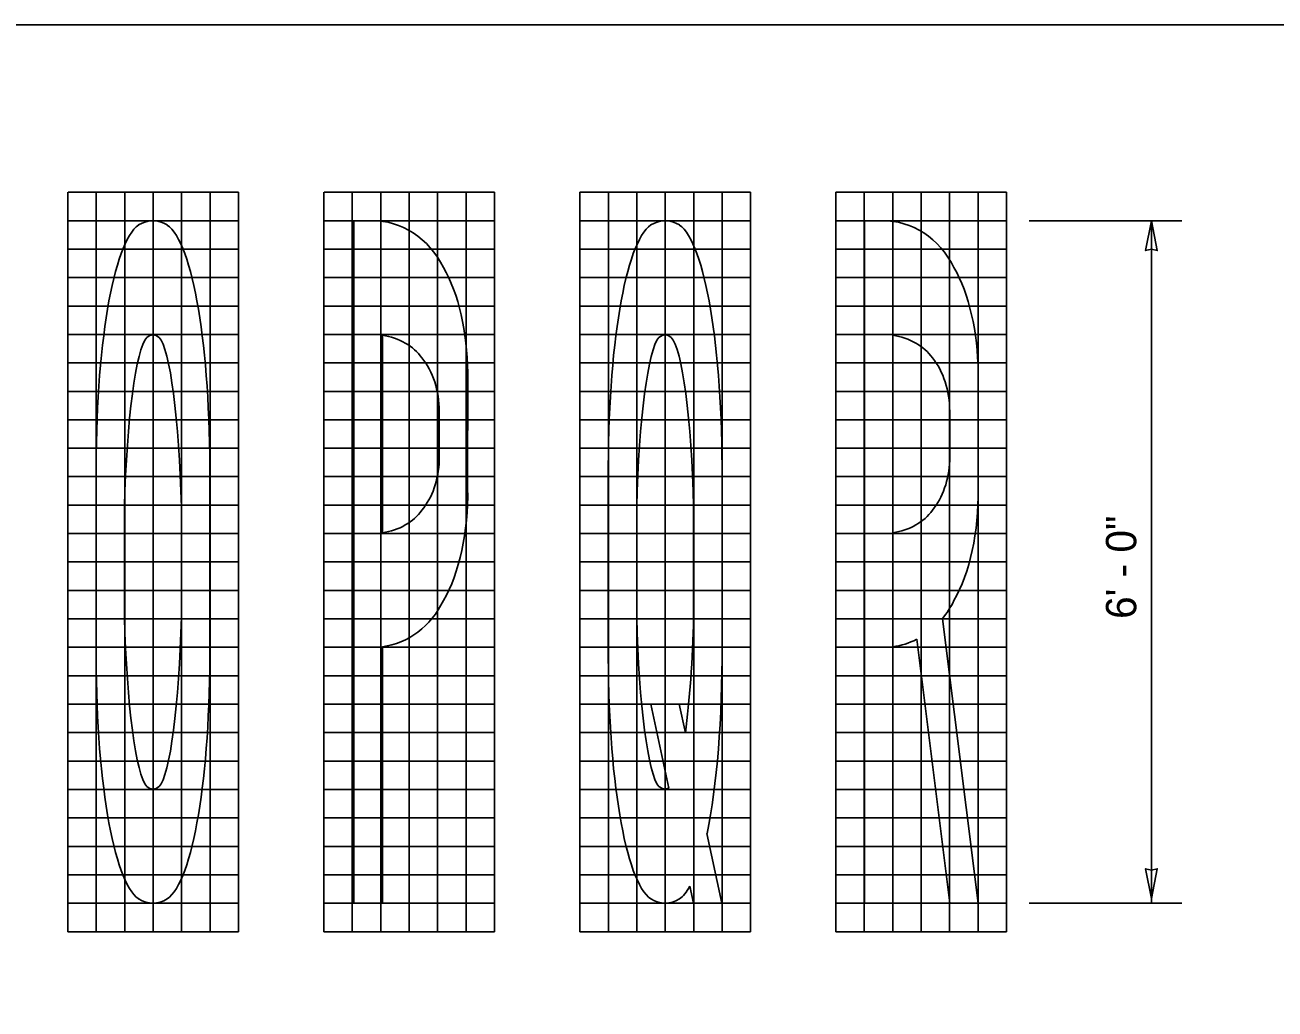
# Model space of a CAD drawing. Extents: x 99862 to 103151, y 100000 to 102076.
# Drawn here: x 101833 to 102492, y 101556 to 102076 of the extents above; entities that cross this region are included whole.
import ezdxf

# ---------------------------------------------------------------- set-up
doc = ezdxf.new("R2010")
doc.units = 0
for name, color, linetype in [('Level 1', 7, 'Continuous'), ('Level 15', 7, 'Continuous'), ('Level 20', 7, 'Continuous'), ('Level 4', 7, 'Continuous')]:
    doc.layers.add(name, color=color, linetype=linetype)

msp = doc.modelspace()

# ---------------------------------------------------------------- linework, layer by layer
at = {"layer": 'Level 1'}
msp.add_lwpolyline([(99862, 99999.5), (103151, 99999.5), (103151, 102075.5), (99862, 102075.5)], close=True, dxfattribs=at)
at = {"layer": 'Level 15'}
for p, q in [((102362.43, 101972.28), (102442.83, 101972.28)), ((102426.83, 101612.28), (102426.83, 101972.28)), ((102362.43, 101612.28), (102442.83, 101612.28))]:
    msp.add_line(p, q, dxfattribs=at)
for points in [[(102426.83, 101972.28), (102423.75, 101956.55), (102426.83, 101957.28), (102429.92, 101956.55)], [(102426.83, 101614.78), (102423.75, 101630.5), (102426.83, 101629.78), (102429.92, 101630.5)]]:
    msp.add_lwpolyline(points, close=True, dxfattribs=at)
at = {"layer": 'Level 20'}
for p, q in [((102013.83, 101972.28), (102006.33, 101972.28)), ((102006.33, 101972.28), (102006.33, 101612.28)), ((102015.72, 101972.27), (102013.83, 101972.28)), ((102282.96, 101972.28), (102275.46, 101972.28)), ((102275.46, 101972.28), (102275.46, 101612.28)), ((102284.86, 101972.27), (102282.96, 101972.28)), ((102021.33, 101807.68), (102021.33, 101911.84)), ((102290.46, 101807.68), (102290.46, 101911.84)), ((102066.31, 101830.95), (102066.33, 101892.06)), ((102335.45, 101830.95), (102335.46, 101892.06)), ((102051.33, 101869.39), (102051.33, 101845.83)), ((102320.46, 101869.39), (102320.46, 101845.83)), ((101870.41, 101836.34), (101870.41, 101792.28)), ((101930.39, 101792.28), (101930.39, 101836.34)), ((102140.44, 101836.34), (102140.44, 101792.28)), ((102200.42, 101748.22), (102200.42, 101836.34)), ((101885.4, 101792.28), (101885.4, 101821.34)), ((101915.4, 101821.34), (101915.4, 101792.28)), ((102155.44, 101763.22), (102155.44, 101821.34)), ((102185.43, 101821.34), (102185.43, 101792.28)), ((101870.41, 101792.28), (101870.41, 101748.22)), ((101885.4, 101763.22), (101885.4, 101792.28)), ((101915.4, 101792.28), (101915.4, 101763.22)), ((101930.39, 101748.22), (101930.39, 101792.28)), ((102140.44, 101792.28), (102140.44, 101748.22)), ((102185.43, 101792.28), (102185.43, 101763.22)), ((102316.71, 101762.28), (102316.46, 101762.28)), ((102335.46, 101612.28), (102316.71, 101762.28)), ((102303.07, 101751.48), (102320.46, 101612.28)), ((102021.33, 101612.28), (102021.33, 101747.57)), ((102290.46, 101612.28), (102290.46, 101747.57)), ((102177.87, 101717.28), (102162.88, 101717.28)), ((102162.88, 101717.28), (102172.37, 101672.98)), ((102181.1, 101702.22), (102177.87, 101717.28)), ((102200.37, 101612.28), (102192.5, 101649.01)), ((102183.45, 101621.24), (102185.37, 101612.28)), ((102006.33, 101612.28), (102021.33, 101612.28)), ((102185.37, 101612.28), (102200.37, 101612.28)), ((102275.46, 101612.28), (102290.46, 101612.28)), ((102320.46, 101612.28), (102335.46, 101612.28))]:
    msp.add_line(p, q, dxfattribs=at)
for centre, major_axis, ratio, start_param, end_param in [((101892.9, 101656.7), (-7.85, -315.58), 0.19927, 3.02647, 3.266464), ((102016.42, 101924.16), (0, -48.11), 0.883106, 2.078693, 3.158066), ((102162.93, 101656.7), (-7.85, -315.58), 0.19927, 3.02647, 3.266464), ((102285.56, 101924.16), (0, -48.11), 0.883106, 2.078693, 3.158066), ((101900.4, 101821.97), (3.75, -149.37), 0.19927, 3.270148, 4.611013), ((101900.41, 101822.04), (-3.72, -149.3), 0.19927, 1.671693, 3.012646), ((102170.43, 101821.97), (3.75, -149.37), 0.19927, 3.270148, 4.611013), ((102170.45, 101822.04), (-3.72, -149.3), 0.19927, 1.671693, 3.012646), ((102030.69, 101891.02), (0, -73.69), 0.483719, 1.584917, 2.445445), ((102299.82, 101891.02), (0, -73.69), 0.483719, 1.584917, 2.445445), ((101896.42, 101821.09), (-2.11, -90.25), 0.122012, 3.268533, 4.71248), ((101894.43, 101651.68), (-6.09, -260.36), 0.122012, 3.042541, 3.248082), ((101904.39, 101821.09), (2.11, -90.25), 0.122012, 1.570705, 3.018849), ((102015.84, 101888.35), (30.13, 0), 0.792657, 0.505828, 1.38755), ((102166.45, 101821.09), (-2.11, -90.25), 0.122012, 3.268533, 4.71248), ((102164.47, 101651.68), (-6.09, -260.36), 0.122012, 3.042541, 3.248082), ((102174.42, 101821.09), (2.11, -90.25), 0.122012, 1.570705, 3.018849), ((102284.97, 101888.35), (30.13, 0), 0.792657, 0.505828, 1.38755), ((102025.89, 101871.67), (0, -36.82), 0.691027, 1.570796, 2.445559), ((102295.02, 101871.67), (0, -36.82), 0.691027, 1.570796, 2.445559), ((102025.89, 101871.67), (0, -36.82), 0.691027, 1.529951, 1.570796), ((102025.88, 101870.07), (2.31, -36.7), 0.691023, 1.508615, 1.52981), ((102295.02, 101871.67), (0, -36.82), 0.691027, 1.529951, 1.570796), ((102295.01, 101870.07), (2.31, -36.7), 0.691023, 1.508615, 1.52981), ((102026.04, 101847.81), (-0.1, -36.69), 0.690438, 0.696034, 1.518966), ((102295.17, 101847.81), (-0.1, -36.69), 0.690438, 0.696034, 1.518966), ((102030.71, 101828.49), (0, -73.71), 0.483307, 0.696034, 1.604189), ((102299.84, 101828.49), (0, -73.71), 0.483307, 0.696034, 1.604189), ((102015.84, 101831.18), (30.13, 0), 0.793333, 4.895635, 5.777357), ((102284.97, 101831.18), (30.13, 0), 0.793333, 4.895635, 5.777357), ((102016.64, 101795.09), (0, -47.81), 0.882353, 0.111341, 1.064968), ((102285.78, 101795.09), (0, -47.81), 0.882353, 0.814442, 1.064968), ((101896.42, 101763.47), (2.11, -90.25), 0.122012, 4.712298, 6.156245), ((101904.39, 101763.47), (-2.11, -90.25), 0.122012, 0.122744, 1.570888), ((102166.45, 101763.47), (2.11, -90.25), 0.122012, 4.712298, 6.156245), ((102174.42, 101763.47), (-2.11, -90.25), 0.122012, 0.827749, 1.570888), ((102285.78, 101795.09), (0, -47.81), 0.882353, 0.111341, 0.422215), ((101900.4, 101762.59), (-3.75, -149.37), 0.19927, 4.813765, 6.15463), ((101900.41, 101762.52), (3.72, -149.3), 0.19927, 0.128946, 1.4699), ((102170.43, 101762.59), (-3.75, -149.37), 0.19927, 4.813765, 6.15463), ((102170.45, 101762.52), (3.72, -149.3), 0.19927, 0.702167, 1.4699), ((101894.43, 101932.88), (6.09, -260.36), 0.122012, 6.176696, 6.382237), ((102164.47, 101932.88), (6.09, -260.36), 0.122012, 6.176696, 6.340383), ((102170.45, 101762.52), (3.72, -149.3), 0.19927, 0.128946, 0.324404), ((101892.9, 101927.86), (7.85, -315.58), 0.19927, 6.158314, 6.398307), ((102162.93, 101927.86), (7.85, -315.58), 0.19927, 6.158314, 6.398307)]:
    msp.add_ellipse(centre, major_axis=major_axis, ratio=ratio, start_param=start_param, end_param=end_param, dxfattribs=at)
at = {"layer": 'Level 4'}
for p, q in [((101855.5, 101987.28), (101855.5, 101597.28)), ((101855.61, 101987.28), (101945.5, 101987.28)), ((101870.5, 101987.28), (101870.5, 101597.28)), ((101885.5, 101987.28), (101885.5, 101597.28)), ((101900.5, 101987.28), (101900.5, 101597.28)), ((101915.5, 101987.28), (101915.5, 101597.28)), ((101930.5, 101987.28), (101930.5, 101597.28)), ((101945.5, 101987.28), (101945.5, 101597.28)), ((101990.5, 101987.28), (101990.5, 101597.28)), ((101990.59, 101987.28), (102080.5, 101987.28)), ((102005.5, 101987.28), (102005.5, 101597.28)), ((102020.5, 101987.28), (102020.5, 101597.28)), ((102035.5, 101987.28), (102035.5, 101597.28)), ((102050.5, 101987.28), (102050.5, 101597.28)), ((102065.5, 101987.28), (102065.5, 101597.28)), ((102080.5, 101987.28), (102080.5, 101597.28)), ((102125.5, 101987.28), (102125.5, 101597.28)), ((102125.52, 101987.28), (102215.5, 101987.28)), ((102140.5, 101987.28), (102140.5, 101597.28)), ((102155.5, 101987.28), (102155.5, 101597.28)), ((102170.5, 101987.28), (102170.5, 101597.28)), ((102185.5, 101987.28), (102185.5, 101597.28)), ((102200.5, 101987.28), (102200.5, 101597.28)), ((102215.5, 101987.28), (102215.5, 101597.28)), ((102260.36, 101987.28), (102350.43, 101987.28)), ((102260.43, 101987.28), (102260.43, 101597.28)), ((102275.43, 101987.28), (102275.43, 101597.28)), ((102290.43, 101987.28), (102290.43, 101597.28)), ((102305.43, 101987.28), (102305.43, 101597.28)), ((102320.43, 101987.28), (102320.43, 101597.28)), ((102335.43, 101987.28), (102335.43, 101597.28)), ((102350.43, 101987.28), (102350.43, 101597.28)), ((101855.43, 101972.28), (101945.5, 101972.28)), ((101990.43, 101972.28), (102080.5, 101972.28)), ((102125.43, 101972.28), (102215.5, 101972.28)), ((102260.36, 101972.28), (102350.43, 101972.28)), ((101855.43, 101957.28), (101945.5, 101957.28)), ((101990.43, 101957.28), (102080.5, 101957.28)), ((102125.43, 101957.28), (102215.5, 101957.28)), ((102260.36, 101957.28), (102350.43, 101957.28)), ((101855.64, 101942.28), (101945.5, 101942.28)), ((101990.64, 101942.28), (102080.5, 101942.28)), ((102125.64, 101942.28), (102215.5, 101942.28)), ((102260.57, 101942.28), (102350.43, 101942.28)), ((101855.43, 101927.28), (101945.5, 101927.28)), ((101990.43, 101927.28), (102080.5, 101927.28)), ((102125.43, 101927.28), (102215.5, 101927.28)), ((102260.36, 101927.28), (102350.43, 101927.28)), ((101855.43, 101912.28), (101945.5, 101912.28)), ((101990.43, 101912.28), (102080.5, 101912.28)), ((102125.43, 101912.28), (102215.5, 101912.28)), ((102260.36, 101912.28), (102350.43, 101912.28)), ((101855.54, 101897.28), (101945.5, 101897.28)), ((101990.54, 101897.28), (102080.5, 101897.28)), ((102125.54, 101897.28), (102215.5, 101897.28)), ((102260.47, 101897.28), (102350.43, 101897.28)), ((101855.54, 101882.28), (101945.5, 101882.28)), ((101990.54, 101882.28), (102080.5, 101882.28)), ((102125.54, 101882.28), (102215.5, 101882.28)), ((102260.47, 101882.28), (102350.43, 101882.28)), ((101855.64, 101867.28), (101945.5, 101867.28)), ((101990.64, 101867.28), (102080.5, 101867.28)), ((102125.64, 101867.28), (102215.5, 101867.28)), ((102260.57, 101867.28), (102350.43, 101867.28)), ((101855.64, 101852.28), (101945.5, 101852.28)), ((101990.64, 101852.28), (102080.5, 101852.28)), ((102125.64, 101852.28), (102215.5, 101852.28)), ((102260.57, 101852.28), (102350.43, 101852.28)), ((101855.43, 101837.28), (101945.5, 101837.28)), ((101990.43, 101837.28), (102080.5, 101837.28)), ((102125.43, 101837.28), (102215.5, 101837.28)), ((102260.36, 101837.28), (102350.43, 101837.28)), ((101855.54, 101822.28), (101945.5, 101822.28)), ((101990.54, 101822.28), (102080.5, 101822.28)), ((102125.54, 101822.28), (102215.5, 101822.28)), ((102260.47, 101822.28), (102350.43, 101822.28)), ((101855.43, 101807.28), (101945.5, 101807.28)), ((101990.43, 101807.28), (102080.5, 101807.28)), ((102125.43, 101807.28), (102215.5, 101807.28)), ((102260.36, 101807.28), (102350.43, 101807.28)), ((101855.54, 101792.28), (101945.5, 101792.28)), ((101990.54, 101792.28), (102080.5, 101792.28)), ((102125.54, 101792.28), (102215.5, 101792.28)), ((102260.47, 101792.28), (102350.43, 101792.28)), ((101855.54, 101777.28), (101945.5, 101777.28)), ((101990.54, 101777.28), (102080.5, 101777.28)), ((102125.54, 101777.28), (102215.5, 101777.28)), ((102260.47, 101777.28), (102350.43, 101777.28)), ((101855.43, 101762.28), (101945.5, 101762.28)), ((101990.43, 101762.28), (102080.5, 101762.28)), ((102125.43, 101762.28), (102215.5, 101762.28)), ((102260.36, 101762.28), (102350.43, 101762.28)), ((101855.54, 101747.28), (101945.5, 101747.28)), ((101990.54, 101747.28), (102080.5, 101747.28)), ((102125.54, 101747.28), (102215.5, 101747.28)), ((102260.47, 101747.28), (102350.43, 101747.28)), ((101855.54, 101732.28), (101945.5, 101732.28)), ((101990.54, 101732.28), (102080.5, 101732.28)), ((102125.54, 101732.28), (102215.5, 101732.28)), ((102260.47, 101732.28), (102350.43, 101732.28)), ((101855.54, 101717.28), (101945.5, 101717.28)), ((101990.54, 101717.28), (102080.5, 101717.28)), ((102125.54, 101717.28), (102215.5, 101717.28)), ((102260.47, 101717.28), (102350.43, 101717.28)), ((101855.54, 101702.28), (101945.5, 101702.28)), ((101990.54, 101702.28), (102080.5, 101702.28)), ((102125.54, 101702.28), (102215.5, 101702.28)), ((102260.47, 101702.28), (102350.43, 101702.28)), ((101855.54, 101687.28), (101945.5, 101687.28)), ((101990.54, 101687.28), (102080.5, 101687.28)), ((102125.54, 101687.28), (102215.5, 101687.28)), ((102260.47, 101687.28), (102350.43, 101687.28)), ((101855.64, 101672.28), (101945.5, 101672.28)), ((101990.64, 101672.28), (102080.5, 101672.28)), ((102125.64, 101672.28), (102215.5, 101672.28)), ((102260.57, 101672.28), (102350.43, 101672.28)), ((101855.54, 101657.28), (101945.5, 101657.28)), ((101990.54, 101657.28), (102080.5, 101657.28)), ((102125.54, 101657.28), (102215.5, 101657.28)), ((102260.47, 101657.28), (102350.43, 101657.28)), ((101855.54, 101642.28), (101945.5, 101642.28)), ((101990.54, 101642.28), (102080.5, 101642.28)), ((102125.54, 101642.28), (102215.5, 101642.28)), ((102260.47, 101642.28), (102350.43, 101642.28)), ((101855.54, 101627.28), (101945.5, 101627.28)), ((101990.54, 101627.28), (102080.5, 101627.28)), ((102125.54, 101627.28), (102215.5, 101627.28)), ((102260.47, 101627.28), (102350.43, 101627.28)), ((101855.43, 101612.28), (101945.5, 101612.28)), ((101990.43, 101612.28), (102080.5, 101612.28)), ((102125.43, 101612.28), (102215.5, 101612.28)), ((102260.36, 101612.28), (102350.43, 101612.28)), ((101855.54, 101597.28), (101945.5, 101597.28)), ((101990.54, 101597.28), (102080.5, 101597.28)), ((102125.54, 101597.28), (102215.5, 101597.28)), ((102260.47, 101597.28), (102350.43, 101597.28))]:
    msp.add_line(p, q, dxfattribs=at)

# ---------------------------------------------------------------- texts
at = {"layer": 'Level 20'}
msp.add_text('6\' - 0" ', height=16, rotation=90, dxfattribs=at).set_placement((102418.83, 101762.24))

doc.saveas('drawing.dxf')
